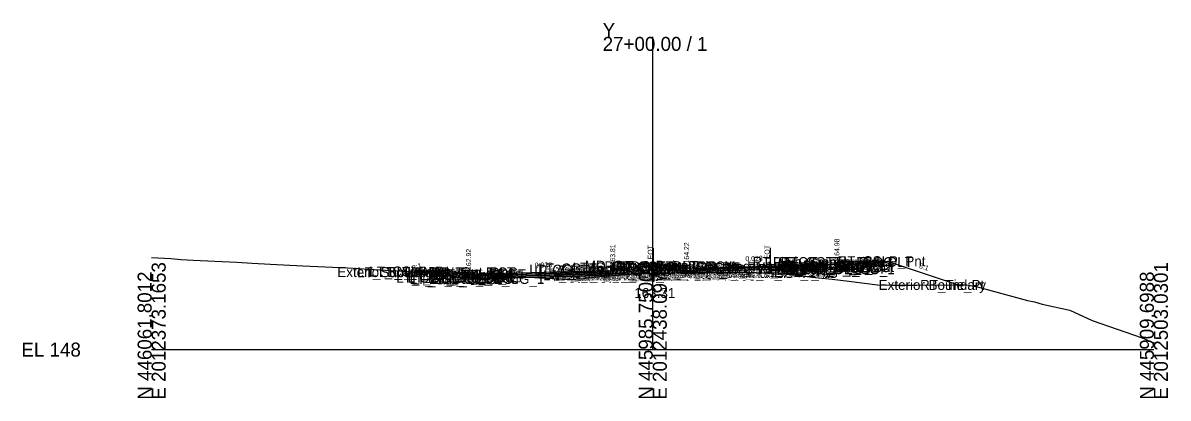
# Model space of a CAD drawing. Extents: x -26 to 3203, y -10 to 9532.
# Drawn here: x 1974.3 to 2202.8, y 990.3 to 1065.3 of the extents above; entities that cross this region are included whole.
import ezdxf

# ---------------------------------------------------------------- set-up
doc = ezdxf.new("R2010")
doc.units = 0
for name, color, linetype in [('Default', 7, 'Continuous'), ('Exist CMT Pavement', 7, 'Continuous'), ('Exist Cross Section Cell', 7, 'Continuous'), ('Exist XS Center Line Elevation Label', 7, 'Continuous'), ('Exist XS Ground Line', 7, 'Continuous'), ('Prop CMT Conc Surface', 7, 'Continuous'), ('Prop CMT Concrete Structures', 7, 'Continuous'), ('Prop CMT Pvmt Course 1', 7, 'Continuous'), ('Prop CMT Pvmt Course 1 CG', 7, 'Continuous'), ('Prop CMT Pvmt Course 2', 7, 'Continuous'), ('Prop CMT Pvmt Course 2 Wedge', 7, 'Continuous'), ('Prop CMT Pvmt Course 3', 7, 'Continuous'), ('Prop CMT Pvmt Course 3 Wedge', 7, 'Continuous'), ('Prop CMT Pvmt Surface', 7, 'Continuous'), ('Prop CMT Slope Grass', 7, 'Continuous'), ('Prop CMT Subgrade Earthwork', 7, 'Continuous'), ('Prop XS Hydro Elevations', 7, 'Continuous'), ('Prop XS Label Text', 7, 'Continuous'), ('Prop XS SE Text', 7, 'Continuous'), ('Prop XS Side Slope Text', 7, 'Continuous'), ('Scratch_Level_0', 7, 'Continuous')]:
    doc.layers.add(name, color=color, linetype=linetype)

msp = doc.modelspace()

# ---------------------------------------------------------------- linework, layer by layer
at = {"layer": 'Exist CMT Pavement'}
msp.add_lwpolyline([(2100.11, 1015.31), (2100.11, 1015.31), (2100.74, 1015.32), (2102.2, 1015.34), (2104.23, 1015.38), (2106.04, 1015.39), (2107.51, 1015.4), (2109.88, 1015.43), (2110.8, 1015.43), (2111.8, 1015.43), (2114, 1015.43), (2115.67, 1015.43), (2117.51, 1015.43), (2120.63, 1015.39), (2121.76, 1015.37), (2123.41, 1015.35)], dxfattribs=at)
at = {"layer": 'Exist Cross Section Cell'}
for p, q in [((2100, 1000), (2100, 1062.5)), ((2000, 1000), (2100, 1000)), ((2100, 1000), (2200, 1000))]:
    msp.add_line(p, q, dxfattribs=at)
at = {"layer": 'Exist XS Ground Line'}
msp.add_lwpolyline([(2000, 1018.44), (2003.84, 1018.2), (2005.9, 1018.02), (2008.3, 1017.9), (2016.99, 1017.47), (2020.08, 1017.26), (2023.7, 1017.05), (2030.14, 1016.73), (2039.1, 1016.32), (2041.36, 1016.19), (2043.29, 1016.1), (2054.51, 1015.4), (2055.55, 1015.34), (2057.49, 1015.26), (2071.3, 1014.82), (2077.29, 1014.37), (2083.91, 1013.99), (2086.12, 1014.2), (2091.49, 1014.85), (2099.07, 1015.3), (2100.11, 1015.31), (2100.74, 1015.32), (2102.2, 1015.34), (2104.23, 1015.38), (2106.04, 1015.39), (2107.51, 1015.4), (2109.88, 1015.43), (2110.8, 1015.43), (2111.8, 1015.43), (2114, 1015.43), (2115.67, 1015.43), (2117.51, 1015.43), (2120.63, 1015.39), (2121.76, 1015.37), (2123.41, 1015.35), (2123.77, 1015.34), (2124.13, 1015.34), (2124.52, 1015.33), (2133.1, 1014.36), (2135.77, 1014.06), (2139.1, 1013.66), (2144.84, 1012.93), (2147.73, 1012.9), (2152.67, 1012.9), (2161.04, 1012.93), (2162.6, 1012.97), (2164.57, 1012.61), (2174.8, 1009.84), (2176.15, 1009.52), (2177.73, 1009.07), (2183.24, 1007.86), (2187.71, 1005.82), (2197.65, 1002.34), (2200, 1001.34)], dxfattribs=at)
at = {"layer": 'Prop CMT Conc Surface'}
for points in [[(2134.75, 1017), (2136.75, 1016.98)], [(2136.75, 1016.98), (2136.75, 1017.48), (2137.25, 1017.48)], [(2058.75, 1015.51), (2053.75, 1015.61)], [(2063.25, 1014.92), (2063.25, 1015.42), (2062.75, 1015.42)], [(2065.25, 1015.06), (2063.25, 1014.92)], [(2091.25, 1015.78), (2092, 1015.81), (2092, 1015.97), (2092.76, 1016.22)], [(2108.75, 1016.27), (2106.75, 1016.22), (2106.75, 1016.38), (2106, 1016.63)]]:
    msp.add_lwpolyline(points, dxfattribs=at)
at = {"layer": 'Prop CMT Concrete Structures'}
for points in [[(2134.75, 1017), (2136.75, 1016.98), (2136.75, 1017.48), (2137.25, 1017.48)], [(2137.25, 1017.48), (2137.25, 1016.49), (2134.75, 1016.42)], [(2134.75, 1016.42), (2134.75, 1017)], [(2145.75, 1017.66), (2137.75, 1017.5)], [(2137.75, 1017.5), (2137.75, 1017.16)], [(2137.75, 1017.16), (2145.75, 1017.32)], [(2145.75, 1017.32), (2145.75, 1017.66)], [(2053.75, 1015.28), (2053.75, 1015.61)], [(2053.75, 1015.61), (2058.75, 1015.51)], [(2058.75, 1015.18), (2053.75, 1015.28)], [(2058.75, 1015.51), (2058.75, 1015.18)], [(2065.25, 1015.06), (2063.25, 1014.92), (2063.25, 1015.42), (2062.75, 1015.42)], [(2062.75, 1015.42), (2062.75, 1014.4), (2065.25, 1014.47)], [(2065.25, 1014.47), (2065.25, 1015.06)], [(2091.25, 1015.78), (2092, 1015.81), (2092, 1015.97), (2092.76, 1016.22)], [(2091.25, 1015.2), (2091.25, 1015.78)], [(2092.76, 1015.24), (2091.25, 1015.2)], [(2092.76, 1016.22), (2092.76, 1015.24)], [(2108.75, 1016.27), (2106.75, 1016.22), (2106.75, 1016.38), (2106, 1016.63)], [(2106, 1016.63), (2106, 1015.61)], [(2106, 1015.61), (2108.75, 1015.69)], [(2108.75, 1015.69), (2108.75, 1016.27)]]:
    msp.add_lwpolyline(points, dxfattribs=at)
at = {"layer": 'Prop CMT Pvmt Course 1'}
for points in [[(2108.75, 1016.27), (2134.75, 1017)], [(2134.75, 1017), (2134.75, 1016.75)], [(2091.25, 1015.78), (2065.25, 1015.06)], [(2065.25, 1014.81), (2091.25, 1015.53)], [(2065.25, 1015.06), (2065.25, 1014.81)], [(2091.25, 1015.53), (2091.25, 1015.78)], [(2091.25, 1015.53), (2091.25, 1015.53), (2091.25, 1015.53)], [(2134.75, 1016.75), (2124.52, 1016.46), (2108.75, 1016.02)], [(2108.75, 1016.02), (2108.75, 1016.27)], [(2108.75, 1016.02), (2108.75, 1016.02)]]:
    msp.add_lwpolyline(points, dxfattribs=at)
at = {"layer": 'Prop CMT Pvmt Course 1 CG'}
for points in [[(2091.25, 1015.2), (2093.26, 1015.26), (2093.58, 1014.93)], [(2091.25, 1014.87), (2091.25, 1015.2)], [(2093.58, 1014.93), (2091.25, 1014.87)], [(2108.75, 1015.69), (2105.5, 1015.6), (2105.16, 1015.26)], [(2105.16, 1015.26), (2108.75, 1015.36)], [(2108.75, 1015.36), (2108.75, 1015.69)], [(2134.75, 1016.42), (2137.75, 1016.5), (2138.07, 1016.18)], [(2134.75, 1016.08), (2134.75, 1016.42)], [(2138.07, 1016.18), (2134.75, 1016.08)], [(2065.25, 1014.47), (2062.25, 1014.39), (2061.91, 1014.05)], [(2061.91, 1014.05), (2065.25, 1014.14)], [(2065.25, 1014.14), (2065.25, 1014.47)]]:
    msp.add_lwpolyline(points, dxfattribs=at)
at = {"layer": 'Prop CMT Pvmt Course 2'}
for points in [[(2091.25, 1015.53), (2065.25, 1014.81)], [(2065.25, 1014.47), (2091.25, 1015.2)], [(2065.25, 1014.81), (2065.25, 1014.47)], [(2091.25, 1015.2), (2091.25, 1015.53)], [(2108.75, 1016.02), (2108.75, 1016.02)], [(2123.41, 1016.43), (2134.75, 1016.75)], [(2123.41, 1016.1), (2123.41, 1016.43)], [(2134.75, 1016.42), (2123.41, 1016.1)], [(2134.75, 1016.75), (2134.75, 1016.42)]]:
    msp.add_lwpolyline(points, dxfattribs=at)
msp.add_lwpolyline([(2108.75, 1016.02), (2108.75, 1015.69), (2108.75, 1015.69)], close=True, dxfattribs=at)
at = {"layer": 'Prop CMT Pvmt Course 2 Wedge'}
msp.add_lwpolyline([(2108.75, 1016.02), (2123.41, 1016.43)], dxfattribs=at)
at = {"layer": 'Prop CMT Pvmt Course 3'}
for points in [[(2091.25, 1015.2), (2065.25, 1014.47)], [(2065.25, 1014.14), (2091.25, 1014.87)], [(2091.25, 1014.87), (2091.25, 1015.2)], [(2108.75, 1015.69), (2108.75, 1015.69), (2108.75, 1015.36), (2108.75, 1015.36)], [(2108.75, 1015.36), (2108.75, 1015.69)], [(2123.41, 1016.1), (2134.75, 1016.42)], [(2123.41, 1015.77), (2123.41, 1016.1)], [(2134.75, 1016.08), (2123.41, 1015.77)], [(2134.75, 1016.42), (2134.75, 1016.08)], [(2065.25, 1014.47), (2065.25, 1014.14)]]:
    msp.add_lwpolyline(points, dxfattribs=at)
at = {"layer": 'Prop CMT Pvmt Course 3 Wedge'}
msp.add_lwpolyline([(2108.75, 1015.69), (2123.41, 1016.1)], dxfattribs=at)
at = {"layer": 'Prop CMT Pvmt Surface'}
for points in [[(2108.75, 1016.27), (2134.75, 1017)], [(2091.25, 1015.78), (2065.25, 1015.06)]]:
    msp.add_lwpolyline(points, dxfattribs=at)
at = {"layer": 'Prop CMT Slope Grass'}
for points in [[(2137.25, 1017.48), (2146.75, 1017.67)], [(2146.75, 1017.67), (2160.95, 1012.93)], [(2053.25, 1015.61), (2052.92, 1015.5)], [(2062.75, 1015.42), (2053.25, 1015.61)], [(2092.76, 1016.22), (2099.38, 1016.77)], [(2106, 1016.63), (2099.38, 1016.77)]]:
    msp.add_lwpolyline(points, dxfattribs=at)
at = {"layer": 'Prop CMT Subgrade Earthwork'}
for points in [[(2134.75, 1016.08), (2138.07, 1016.18), (2139.42, 1017.52)], [(2065.25, 1014.14), (2061.91, 1014.05), (2060.49, 1015.47)], [(2091.25, 1014.87), (2065.25, 1014.14)], [(2093.58, 1014.93), (2091.25, 1014.87)], [(2091.25, 1014.87), (2091.25, 1014.87)], [(2091.25, 1014.87), (2091.25, 1014.87)], [(2095.06, 1016.41), (2093.58, 1014.93)], [(2103.73, 1016.68), (2105.16, 1015.26)], [(2105.16, 1015.26), (2108.75, 1015.36)], [(2108.75, 1015.36), (2108.73, 1015.41)], [(2108.75, 1015.36), (2108.75, 1015.36)], [(2108.75, 1015.36), (2108.75, 1015.36)], [(2123.41, 1015.77), (2134.75, 1016.08)], [(2123.41, 1015.77), (2123.42, 1015.35)], [(2134.75, 1016.08), (2134.75, 1016.08)], [(2065.25, 1014.14), (2065.25, 1014.14)]]:
    msp.add_lwpolyline(points, dxfattribs=at)
at = {"layer": 'Prop XS Label Text'}
for p, q in [((2100.11, 1020.31), (2100.11, 1015.31)), ((2123.41, 1020.35), (2123.41, 1015.35))]:
    msp.add_line(p, q, dxfattribs=at)

# ---------------------------------------------------------------- texts
at = {"layer": 'Default'}
msp.add_text('-', height=0.0001, dxfattribs=at).set_placement((2000, 1000))
at = {"layer": 'Exist Cross Section Cell'}
for s, p in [('Y', (2090, 1062.5)), ('27+00.00 / 1', (2090, 1059.7)), ('EL 148', (1974, 998.6))]:
    msp.add_text(s, height=2.8, dxfattribs=at).set_placement(p)
for s, p in [('E 2012373.1653', (2002.8, 990)), ('E 2012438.0977', (2102.8, 990)), ('E 2012503.0301', (2202.8, 990)), ('N 446061.8012', (2000, 990)), ('N 445985.7500', (2100, 990)), ('N 445909.6988', (2200, 990))]:
    msp.add_text(s, height=2.8, rotation=90, dxfattribs=at).set_placement(p)
at = {"layer": 'Exist XS Center Line Elevation Label'}
msp.add_text('163.31', height=2, dxfattribs=at).set_placement((2096.32, 1010.31))
at = {"layer": 'Prop XS Hydro Elevations'}
for s, p in [('164.98', (2137.25, 1017.98)), ('162.92', (2063.75, 1015.92)), ('163.81', (2092.5, 1016.81)), ('164.22', (2107.25, 1017.22))]:
    msp.add_text(s, height=1, rotation=90, dxfattribs=at).set_placement(p)
at = {"layer": 'Prop XS Label Text'}
for p in [(2100.01, 1016.34), (2123.31, 1016.38)]:
    msp.add_text('E. EOT', height=1, rotation=90, dxfattribs=at).set_placement(p)
at = {"layer": 'Prop XS SE Text'}
for p in [(2076.48, 1016.37), (2118.5, 1017.67)]:
    msp.add_text('0.028', height=1, rotation=1.6027, dxfattribs=at).set_placement(p)
at = {"layer": 'Prop XS Side Slope Text'}
for rotation, p in [(18.4349, (2052.19, 1015.83)), (18.4349, (2052.19, 1015.83)), (341.5651, (2153.07, 1016.35))]:
    msp.add_text('3:1', height=1, rotation=rotation, dxfattribs=at).set_placement(p)
at = {"layer": 'Scratch_Level_0'}
for s, p in [('LT_CG_Top_Face_Med', (2075.37, 1014.97)), ('LT_CG_Top_BOC_Med', (2077.15, 1015.22)), ('LT_Sub_DLT_In', (2084.01, 1015.41)), ('MD_Crown Point', (2086.45, 1015.77)), ('RT_CG_Top_BOC_Med', (2090.35, 1015.63)), ('RT_CG_Top_BOC In', (2091.97, 1015.63)), ('RT_CG_Top FOC In', (2092.61, 1015.38)), ('RT_Sub_DLT_In', (2092.63, 1015.68)), ('RT_CG_Top_Gut In', (2092.64, 1015.22)), ('RT_PV2_IEEOP', (2098.66, 1015.02)), ('RT_PV2_PGL', (2099.92, 1015.02)), ('RT_PV1_PGL', (2100.48, 1015.27)), ('RT_PV2_OEEOP', (2113.78, 1015.46)), ('RT_PV3_OEEOP', (2113.78, 1015.13)), ('RT_Sub_Trench_Out_DLT', (2119.94, 1016.52)), ('RT_Sub_OEOT_CG_1', (2120.92, 1015.08)), ('RT_CG_Top_Face', (2123.96, 1016.48)), ('RT_CG1_Shelf_Out', (2124.25, 1015.5)), ('RT_CG_Bot_IE', (2124.62, 1015.42)), ('RT_Sub_OEOT', (2124.78, 1015.08)), ('RT_PV2_OEOT', (2124.88, 1015.75)), ('RT_PV3_OEOT', (2124.88, 1015.42)), ('RT_CG_Top_Gut', (2124.94, 1015.98)), ('RT_PV1_OEOT', (2125.44, 1016)), ('RT_CG_Top_BOC', (2125.49, 1016.48)), ('RT_CG_Bot_BOC', (2125.52, 1015.49)), ('RT_Sub_OEOP', (2128.14, 1015.18)), ('RT_CSLP_Pnt', (2136.88, 1016.67)), ('Exterior Boundary', (2037.06, 1014.5)), ('LT_Sub_Trench_Out_DLT', (2041.05, 1014.47)), ('LT_CSLP_Pnt', (2043.42, 1014.61)), ('LT_Tie_Pt', (2045.36, 1014.5)), ('LT_CG1_Shelf_Out', (2048.8, 1013.39)), ('LT_CG_Top_Face', (2050.51, 1014.42)), ('LT_CG_Top_BOC', (2051.03, 1014.42)), ('LT_CG_Bot_BOC', (2051.06, 1013.4)), ('LT_Sub_OEOT_CG_1', (2051.47, 1013.14)), ('LT_CG_Top_Gut', (2051.49, 1013.92)), ('LT_Sub_OEOP', (2052.02, 1013.05)), ('LT_CG_Bot_IE', (2055.16, 1013.47)), ('LT_Sub_OEOT', (2055.33, 1013.14)), ('LT_PV2_OEOT', (2055.42, 1013.81)), ('LT_PV3_OEOT', (2055.42, 1013.47)), ('LT_PV1_OEOT', (2055.99, 1014.06)), ('LT_CG_Top_Gut_Med', (2076.35, 1014.81)), ('LT_CG_Bot_BOC_Med', (2077.19, 1014.24)), ('LT_CG_Bot_IE_Med', (2077.31, 1014.2)), ('LT_Sub_IEOT_CG_1', (2078.12, 1013.87)), ('LT_Sub_OEEOP', (2080.46, 1013.87)), ('LT_PV2_OEEOP', (2080.56, 1014.53)), ('LT_PV3_OEEOP', (2080.56, 1014.2)), ('LT_Sub_IEEOP', (2081.11, 1013.87)), ('LT_PV2_IEEOP', (2081.2, 1014.53)), ('LT_CG1_Shelf_In', (2081.43, 1014.26)), ('LT_Sub_PGL', (2082.37, 1013.87)), ('LT_PV2_PGL', (2082.46, 1014.53)), ('LT_PV1_PGL', (2083.03, 1014.78)), ('LT_Sub_IEOP', (2084.34, 1013.93)), ('RT_CG_Bot BOC In', (2091.84, 1014.61)), ('RT_CG1_Shelf_In', (2093.63, 1014.6)), ('RT_CG_Bot_IE_Med', (2094.77, 1014.69)), ('RT_PV_Sub_Tie_In', (2095.25, 1014.41)), ('RT_Sub_IEOT_CG_1', (2095.57, 1014.36)), ('RT_Sub_IEOP', (2095.87, 1014.26)), ('RT_PV_IEEOP_EG', (2096.89, 1014.41)), ('RT_Sub_IEEOP', (2098.56, 1014.36)), ('RT_PV3_IEEOP', (2098.66, 1014.69)), ('RT_Sub_PGL', (2099.82, 1014.36)), ('RT_PV3_PGL', (2099.92, 1014.69)), ('RT_PV_Sub_Tie_Out', (2109.43, 1014.33)), ('RT_PV_OEEOP_EG', (2112.01, 1014.33)), ('RT_Sub_OEEOP', (2113.68, 1014.8)), ('Exterior Boundary', (2145.09, 1011.93)), ('RT_Tie_Pt', (2153.35, 1011.93))]:
    msp.add_text(s, height=2, dxfattribs=at).set_placement(p)

doc.saveas('drawing.dxf')
